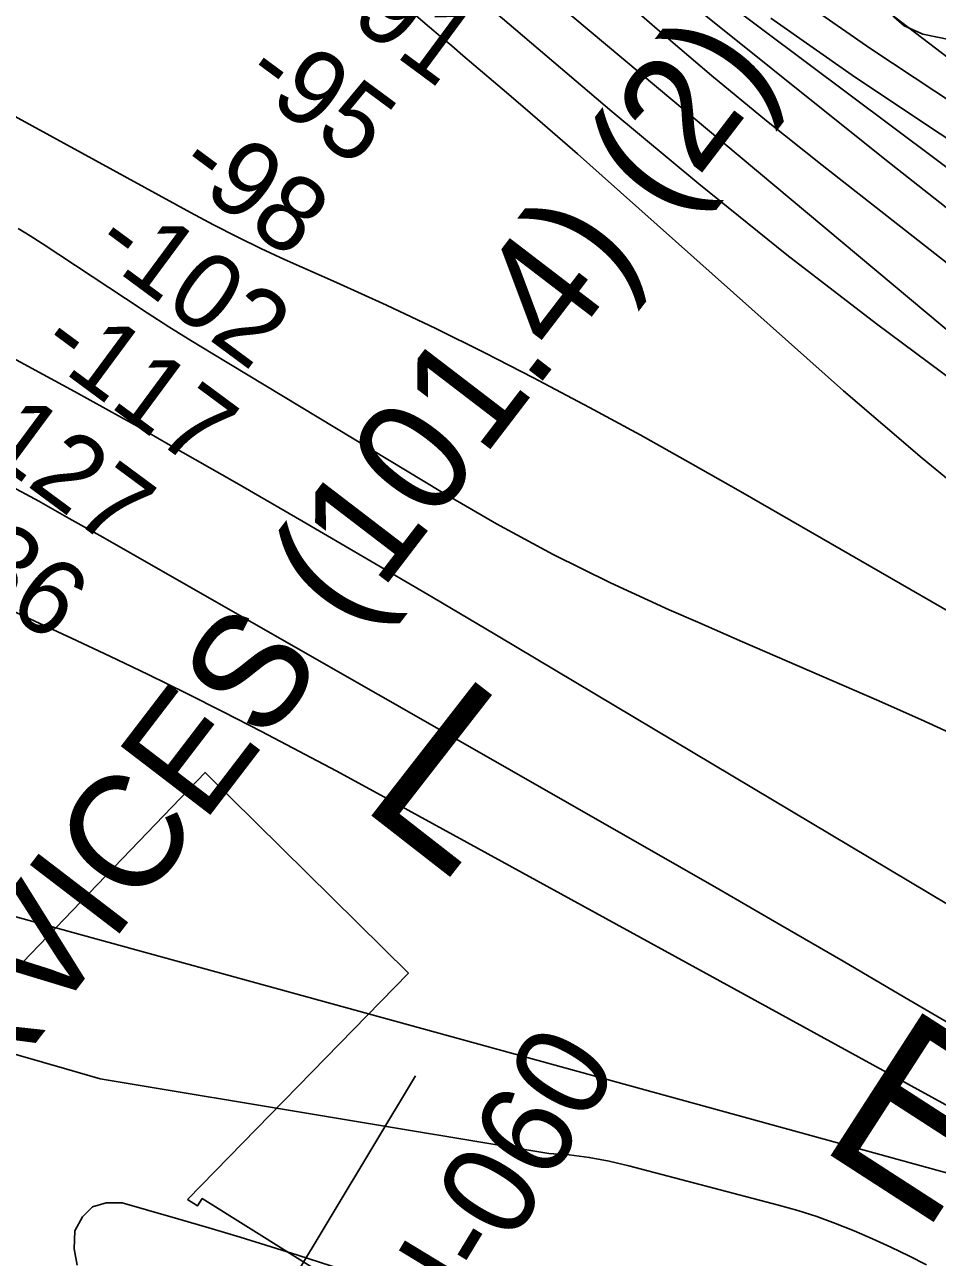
# Model space of a CAD drawing. Extents: x 3651524 to 3689615, y 505651 to 531377.
# Drawn here: x 3660133 to 3660942, y 515987 to 517079 of the extents above; entities that cross this region are included whole.
import ezdxf

# ---------------------------------------------------------------- set-up
doc = ezdxf.new("R2010")
doc.units = 0
for name, color, linetype in [('V-CHAN-NAID', 7, 'Continuous'), ('V-GRID-MAJR', 7, 'Continuous'), ('V-RIVR-EDGE', 7, 'Continuous'), ('V-RIVR-IDEN', 7, 'Continuous'), ('V-RIVR-RANG', 7, 'Continuous'), ('V-RIVR-RANG-IDEN', 7, 'Continuous'), ('V-RRAP-RVMT', 7, 'Continuous'), ('V-TOPO-DPTH', 7, 'Continuous'), ('V-TOPO-MAJR', 7, 'Continuous'), ('V-TOPO-MINR', 7, 'Continuous')]:
    doc.layers.add(name, color=color, linetype=linetype)

msp = doc.modelspace()

# ---------------------------------------------------------------- linework, layer by layer
at = {"layer": 'V-GRID-MAJR'}
msp.add_spline([(3661045.474, 511119.283), (3660982.023, 517177.978), (3660918.553, 523238.605), (3660855.082, 529299.245), (3660855.062, 529301.164)], degree=3, dxfattribs=at)
at = {"layer": 'V-RIVR-EDGE'}
msp.add_lwpolyline([(3660953.456, 517065.584), (3660928.959, 517070.546), (3660912.434, 517077.94), (3660903.262, 517085.928)], dxfattribs=at)
at = {"layer": 'V-RIVR-RANG'}
msp.add_line((3659828.666, 515068.764), (3660479.498, 516147.66), dxfattribs=at)
at = {"layer": 'V-RRAP-RVMT'}
for points in [[(3660087.089, 516202.755), (3660293.017, 516416.547), (3660473.064, 516238.798), (3660277.41, 516038.196)], [(3660277.41, 516038.196), (3660286.302, 516032.663), (3660290.402, 516039.127), (3660408.898, 515965.164)]]:
    msp.add_lwpolyline(points, dxfattribs=at)
at = {"layer": 'V-TOPO-DPTH'}
for points in [[(3662523.713, 516153.78), (3662385.315, 516204.822), (3662374.579, 516208.864), (3662363.881, 516213.002), (3662353.24, 516217.285), (3662342.637, 516221.664), (3661744.618, 516473.412), (3661688.455, 516497.47), (3661632.498, 516521.992), (3661576.852, 516547.212), (3661521.413, 516572.897), (3661482.077, 516591.421), (3661446.787, 516608.79), (3661411.927, 516626.953), (3661377.715, 516646.308), (3661343.935, 516666.456), (3661310.77, 516687.629), (3661277.992, 516709.369), (3661245.795, 516731.961), (3661213.986, 516755.121), (3660591.21, 517221.17)], [(3662523.713, 516153.78), (3662385.315, 516204.822), (3662374.579, 516208.864), (3662363.881, 516213.002), (3662353.24, 516217.285), (3662342.637, 516221.664), (3661744.618, 516473.412), (3661688.455, 516497.47), (3661632.498, 516521.992), (3661576.852, 516547.212), (3661521.413, 516572.897), (3661482.077, 516591.421), (3661446.787, 516608.79), (3661411.927, 516626.953), (3661377.715, 516646.308), (3661343.935, 516666.456), (3661310.77, 516687.629), (3661277.992, 516709.369), (3661245.795, 516731.961), (3661213.986, 516755.121), (3660591.21, 517221.17)], [(3662181.512, 516408.666), (3662176.375, 516408.763), (3662163.722, 516410.628), (3662151.878, 516412.726), (3662140.146, 516415.274), (3662128.581, 516418.497), (3662117.127, 516422.17), (3662079.762, 516435.359), (3662049.709, 516445.962), (3662019.653, 516456.558), (3661989.594, 516467.144), (3661959.533, 516477.724), (3661861.762, 516512.116), (3661791.077, 516537.993), (3661720.865, 516565.054), (3661651.362, 516593.888), (3661582.333, 516623.905), (3661456.758, 516680.417), (3661450.947, 516683.203), (3661445.237, 516686.171), (3661439.677, 516689.413), (3661434.216, 516692.836), (3660882.802, 517057.461), (3660834.587, 517090.752)], [(3661434.216, 516692.836), (3660882.802, 517057.461), (3660834.587, 517090.752)], [(3660794.309, 517084.713), (3660866.208, 517034.193), (3660939.286, 516985.395), (3661013.15, 516937.743), (3661412.128, 516687.012), (3661424.675, 516679.465), (3661437.403, 516672.252), (3661450.402, 516665.542), (3661463.583, 516659.167), (3662159.417, 516339.203), (3662181.63, 516329.22), (3662203.953, 516319.494), (3662226.439, 516310.154), (3662249.036, 516301.072), (3662281.23, 516288.453), (3662287.824, 516285.907), (3662294.435, 516283.407), (3662301.071, 516280.975), (3662307.723, 516278.588), (3662316.013, 516275.662), (3662318.552, 516274.847), (3662321.117, 516274.133), (3662323.718, 516273.568)], [(3660794.309, 517084.713), (3660866.208, 517034.193), (3660939.286, 516985.395), (3661013.15, 516937.743), (3661412.128, 516687.012), (3661424.675, 516679.465), (3661437.403, 516672.252), (3661450.402, 516665.542), (3661463.583, 516659.167), (3662159.417, 516339.203), (3662181.63, 516329.22), (3662203.953, 516319.494), (3662226.439, 516310.154), (3662249.036, 516301.072), (3662281.23, 516288.453), (3662287.824, 516285.907), (3662294.435, 516283.407), (3662301.071, 516280.975), (3662307.723, 516278.588), (3662316.013, 516275.662), (3662318.552, 516274.847), (3662321.117, 516274.133), (3662323.718, 516273.568), (3664164.433, 515692.133)]]:
    msp.add_lwpolyline(points, dxfattribs=at)
at = {"layer": 'V-TOPO-MAJR'}
for points in [[(3660980.519, 516542.603), (3660767.385, 516665.396), (3660723.013, 516690.61), (3660678.446, 516715.468), (3660633.585, 516739.794), (3660588.53, 516763.766), (3660584.036, 516766.123), (3660540.873, 516788.22), (3660497.435, 516809.746), (3660453.582, 516830.414), (3660409.452, 516850.51), (3660363.439, 516870.921), (3660342.252, 516880.67), (3660321.257, 516890.803), (3660300.549, 516901.51), (3660280.032, 516912.6), (3659497.317, 517340.937)], [(3663091.602, 515904.043), (3662410.322, 516148.275), (3662378.378, 516159.927), (3662346.523, 516171.815), (3662314.803, 516184.057), (3662283.171, 516196.533), (3662170.459, 516241.717), (3662082.843, 516277.665), (3661995.633, 516314.55), (3661909.03, 516352.842), (3661822.833, 516392.07), (3661410.748, 516583.647), (3661401.723, 516588.147), (3661392.882, 516592.964), (3661384.317, 516598.256), (3661375.935, 516603.865), (3661224.76, 516711.143), (3661141.472, 516771.35), (3661058.907, 516832.514), (3660977.426, 516895.116), (3660896.668, 516958.675), (3660593.244, 517201.812)], [(3661098.895, 515983.752), (3661090.483, 515988.755), (3661082.032, 515993.693), (3661067.89, 516001.845), (3661065.177, 516003.391), (3661062.455, 516004.92), (3661059.717, 516006.422), (3661056.97, 516007.906), (3661027.301, 516023.746), (3661009.66, 516033.036), (3660991.951, 516042.191), (3660974.138, 516051.144), (3660956.257, 516059.962), (3660013.267, 516319.219)]]:
    msp.add_lwpolyline(points, dxfattribs=at)
at = {"layer": 'V-TOPO-MINR'}
for points in [[(3661113.011, 516926.349), (3660654.295, 517276.185)], [(3662523.713, 516153.78), (3662385.315, 516204.822), (3662374.579, 516208.864), (3662363.881, 516213.002), (3662353.24, 516217.285), (3662342.637, 516221.664), (3661744.618, 516473.412), (3661688.455, 516497.47), (3661632.498, 516521.992), (3661576.852, 516547.212), (3661521.413, 516572.897), (3661482.077, 516591.421), (3661446.787, 516608.79), (3661411.927, 516626.953), (3661377.715, 516646.308), (3661343.935, 516666.456), (3661310.77, 516687.629), (3661277.992, 516709.369), (3661245.795, 516731.961), (3661213.986, 516755.121), (3660591.21, 517221.17)], [(3663009.808, 515829.473), (3662371.641, 516056.175), (3662339.621, 516067.766), (3662307.698, 516079.611), (3662275.918, 516091.836), (3662244.234, 516104.316), (3662131.994, 516149.303), (3662044.581, 516185.201), (3661957.592, 516222.076), (3661871.239, 516260.417), (3661785.311, 516299.737), (3661361.187, 516498.164), (3661352.78, 516502.396), (3661344.556, 516506.939), (3661336.607, 516511.948), (3661328.841, 516517.266), (3661219.532, 516596.85), (3661157.73, 516642.809), (3661096.566, 516689.585), (3661036.361, 516737.589), (3660976.793, 516786.41), (3660528.364, 517161.584)], [(3662469.462, 516070.651), (3662344.372, 516117.443), (3662335.441, 516120.836), (3662326.533, 516124.288), (3662317.661, 516127.831), (3662308.813, 516131.435), (3661567.887, 516437.531), (3661532.897, 516452.79), (3661498.344, 516468.937), (3661464.445, 516486.416), (3661430.982, 516504.783), (3661398.308, 516524.501), (3661366.245, 516545.126), (3661335.099, 516567.111), (3661304.564, 516590.003), (3660839.766, 516954.344), (3660790.43, 516993.784), (3660741.61, 517033.841), (3660693.565, 517074.823), (3660646.036, 517116.423)], [(3660999.199, 516636.76), (3660928.261, 516694.787), (3660858.684, 516754.54), (3660644.904, 516944.924), (3660622.909, 516964.373), (3660600.822, 516983.716), (3660578.597, 517002.901), (3660556.282, 517021.982), (3660531.211, 517043.264), (3660521.363, 517051.626), (3660511.517, 517059.989), (3660501.672, 517068.354), (3660491.829, 517076.72), (3660477.513, 517088.891)], [(3662467.401, 515962.496), (3662305.039, 516026.006), (3662296.519, 516029.384), (3662288.021, 516032.816), (3662279.554, 516036.326), (3662271.11, 516039.89), (3661998.472, 516156.436), (3661885.267, 516206.615), (3661773.01, 516258.768), (3661662.177, 516313.881), (3661552.293, 516370.966), (3661368.829, 516469.39), (3661351.605, 516479.09), (3661334.667, 516489.246), (3661318.158, 516500.086), (3661301.936, 516511.382), (3660968.38, 516753.937), (3660887.987, 516813.821), (3660808.545, 516874.911), (3660730.526, 516937.809), (3660653.458, 517001.914), (3660542.617, 517096.285)], [(3662181.512, 516408.666), (3662176.375, 516408.763), (3662163.722, 516410.628), (3662151.878, 516412.726), (3662140.146, 516415.274), (3662128.581, 516418.497), (3662117.127, 516422.17), (3662079.762, 516435.359), (3662049.709, 516445.962), (3662019.653, 516456.558), (3661989.594, 516467.144), (3661959.533, 516477.724), (3661861.762, 516512.116), (3661791.077, 516537.993), (3661720.865, 516565.054), (3661651.362, 516593.888), (3661582.333, 516623.905), (3661456.758, 516680.417), (3661450.947, 516683.203), (3661445.237, 516686.171), (3661439.677, 516689.413), (3661434.216, 516692.836), (3660882.802, 517057.461), (3660834.587, 517090.752)], [(3662323.718, 516273.568), (3662321.117, 516274.133), (3662318.552, 516274.847), (3662316.013, 516275.662), (3662307.723, 516278.588), (3662301.071, 516280.975), (3662294.435, 516283.407), (3662287.824, 516285.907), (3662281.23, 516288.453), (3662249.036, 516301.072), (3662226.439, 516310.154), (3662203.953, 516319.494), (3662181.63, 516329.22), (3662159.417, 516339.203), (3661463.583, 516659.167), (3661450.402, 516665.542), (3661437.403, 516672.252), (3661424.675, 516679.465), (3661412.128, 516687.012), (3661013.15, 516937.743), (3660939.286, 516985.395), (3660866.208, 517034.193), (3660794.309, 517084.713)], [(3660966.404, 516445.471), (3660927.291, 516463.52), (3660887.903, 516480.99), (3660848.321, 516498.055), (3660808.757, 516515.159), (3660769.218, 516532.324), (3660729.697, 516549.528), (3660704.114, 516560.687), (3660652.334, 516584.506), (3660601.244, 516609.661), (3660551.191, 516636.818), (3660501.828, 516665.31), (3660299.897, 516787.26), (3660280.344, 516799.234), (3660260.893, 516811.369), (3660241.594, 516823.743), (3660222.396, 516836.278), (3660148.492, 516885.189), (3660137.931, 516891.868), (3660127.202, 516898.249)], [(3661074.006, 516226.301), (3660551.188, 516538.025), (3660493.843, 516572.021), (3660436.385, 516605.824), (3660378.756, 516639.336), (3660321.015, 516672.655), (3660260.381, 516707.44), (3660232.811, 516723.111), (3660205.158, 516738.634), (3660177.382, 516753.936), (3660149.524, 516769.09), (3660068.25, 516812.881)], [(3660976.717, 516179.952), (3660913.128, 516217.267), (3660858.205, 516249.365), (3660803.205, 516281.331), (3660748.092, 516313.1), (3660692.902, 516344.738), (3660199.691, 516626.302), (3660172.645, 516641.59), (3660145.514, 516656.725), (3660118.255, 516671.629)], [(3661250.409, 515952.496), (3661133.544, 516019.87), (3661109.826, 516033.44), (3661086.049, 516046.908), (3661062.185, 516060.219), (3661038.262, 516073.426), (3660442.145, 516400.001), (3660409.191, 516417.857), (3660376.129, 516435.508), (3660342.905, 516452.852), (3660309.573, 516469.991), (3660276.07, 516486.791), (3660242.447, 516503.345), (3660208.644, 516519.527), (3660174.721, 516535.462), (3660121.748, 516559.991)], [(3660932.224, 515980.376), (3660916.42, 515988.394), (3660900.488, 515996.137), (3660884.361, 516003.468), (3660868.105, 516010.523), (3660851.633, 516017.021), (3660835.002, 516023.052), (3660818.134, 516028.384), (3660801.108, 516033.25), (3660668.527, 516068.156), (3660650.974, 516072.194), (3660633.306, 516075.491), (3660615.467, 516077.675), (3660597.513, 516079.119), (3660199.975, 516145.085), (3660170.586, 516153.626), (3660019.207, 516196.979)], [(3660414.463, 515976.312), (3660375.251, 515989.012), (3660351.555, 515996.348), (3660323.981, 516004.776), (3660296.368, 516013.074), (3660268.697, 516021.174), (3660240.987, 516029.144), (3660219.445, 516035.256), (3660205.251, 516035.362), (3660193.174, 516031.875), (3660184.272, 516023), (3660177.487, 516010.533), (3660176.837, 515994.632), (3660179.526, 515979.998)]]:
    msp.add_lwpolyline(points, dxfattribs=at)

# ---------------------------------------------------------------- texts
at = {"layer": 'V-CHAN-NAID'}
for s, rotation, p in [('WESTWEGO WATER INTAKE (101.5)', 36.085782, (3659206.87, 516652.24)), ('ST SERVICES (101.4) (2)', 52.555239, (3659861.831, 515809.781))]:
    msp.add_text(s, height=100, rotation=rotation, dxfattribs=at).set_placement(p)
at = {"layer": 'V-RIVR-IDEN'}
for s, rotation, p in [('L', 322.088807, (3660427.31, 516388.402)), ('E', 327.147124, (3660833.376, 516086.18))]:
    msp.add_text(s, height=150, rotation=rotation, dxfattribs=at).set_placement(p)
at = {"layer": 'V-RIVR-RANG'}
for s, p in [('-91', (3660396.269, 517099.14)), ('-95', (3660324.096, 517028.139)), ('-98', (3660265.286, 516947.257)), ('-102', (3660190.781, 516877.982)), ('-117', (3660142.999, 516788.944)), ('-127', (3660069.766, 516718.728)), ('-136', (3660011.803, 516637.218))]:
    msp.add_text(s, height=67, rotation=323.515472, dxfattribs=at).set_placement(p)
at = {"layer": 'V-RIVR-RANG-IDEN'}
msp.add_text('U-060', height=83, rotation=58.758326, dxfattribs=at).set_placement((3660503.869, 515897.725))

doc.saveas('drawing.dxf')
